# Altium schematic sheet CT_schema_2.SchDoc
size 284 x 147 mm
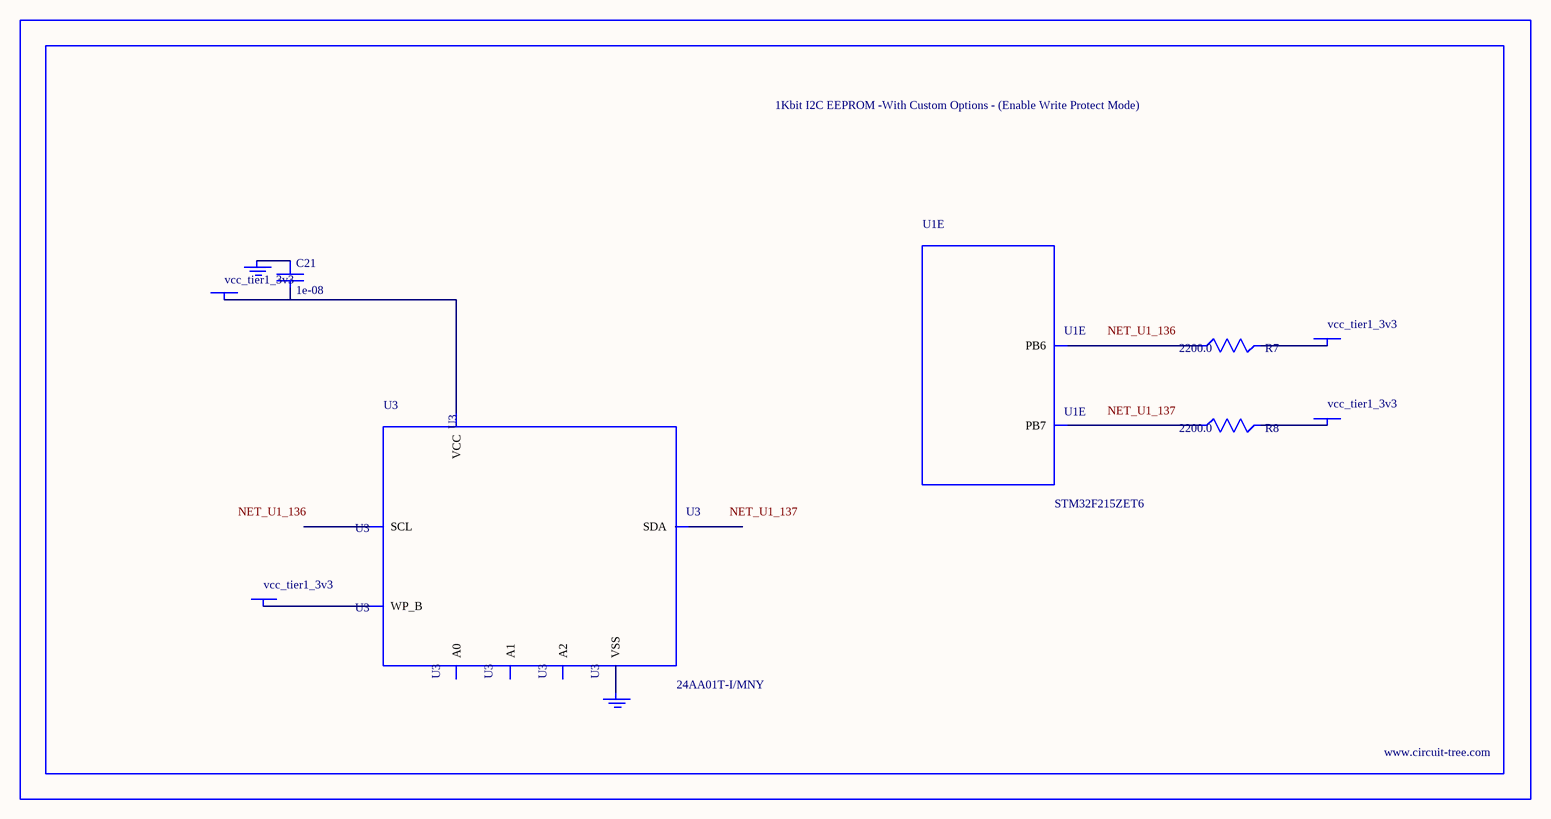
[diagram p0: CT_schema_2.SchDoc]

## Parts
BORDER1  (no value)
C21  1e-08  [C0402]
GND_INSTANCE_1_0  (no value)
GND_INSTANCE_1_1  (no value)
POWER_INSTANCE_1_0  vcc_tier1_3v3
POWER_INSTANCE_1_1  vcc_tier1_3v3
POWER_INSTANCE_1_2  vcc_tier1_3v3
POWER_INSTANCE_1_3  vcc_tier1_3v3
R7  2200.0  [R0603]
R8  2200.0  [R0603]
U1  STM32F215ZET6  [LQFP144]  (part E of 12)
U3  24AA01T-I/MNY  [TDFN-8/6MM]

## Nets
NetC21_1: C21.1 GND_INSTANCE_1_0.0(GND)
NetC21_2: C21.2 POWER_INSTANCE_1_1.0(PWR) U3.8(VCC)
NetGND_INSTANCE_1_1_0: GND_INSTANCE_1_1.0(GND) U3.4(VSS)
NetPOWER_INSTANCE_1_0_0: POWER_INSTANCE_1_0.0(PWR) U3.7(WP_B)
NetPOWER_INSTANCE_1_2_0: POWER_INSTANCE_1_2.0(PWR) R7.2
NetPOWER_INSTANCE_1_3_0: POWER_INSTANCE_1_3.0(PWR) R8.2
NetR7_1: R7.1 U1.136(PB6)
NetR8_1: R8.1 U1.137(PB7)

Not connected (* = marked no-connect by the designer): U3 1(A0) 2(A1) 3(A2) 5(SDA) 6(SCL)

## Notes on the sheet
- Labels drawn without touching a wire or pin: NET_U1_136, NET_U1_137

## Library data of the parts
BORDER1 = BORDER_PAGE1
C21 = C0402C103K3RAC
GND_INSTANCE_1_0 GND_INSTANCE_1_1 = GND
POWER_INSTANCE_1_0-POWER_INSTANCE_1_3 = PWR
R7 R8 = RC0603JR-072K2L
